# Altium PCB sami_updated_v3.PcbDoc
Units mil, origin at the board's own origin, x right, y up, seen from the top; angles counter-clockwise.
Board outline 1157.48 x 610 mil, 2 copper layers (Top Layer, Bottom Layer); 22 components, 24 nets, 105 pads, 51 vias.
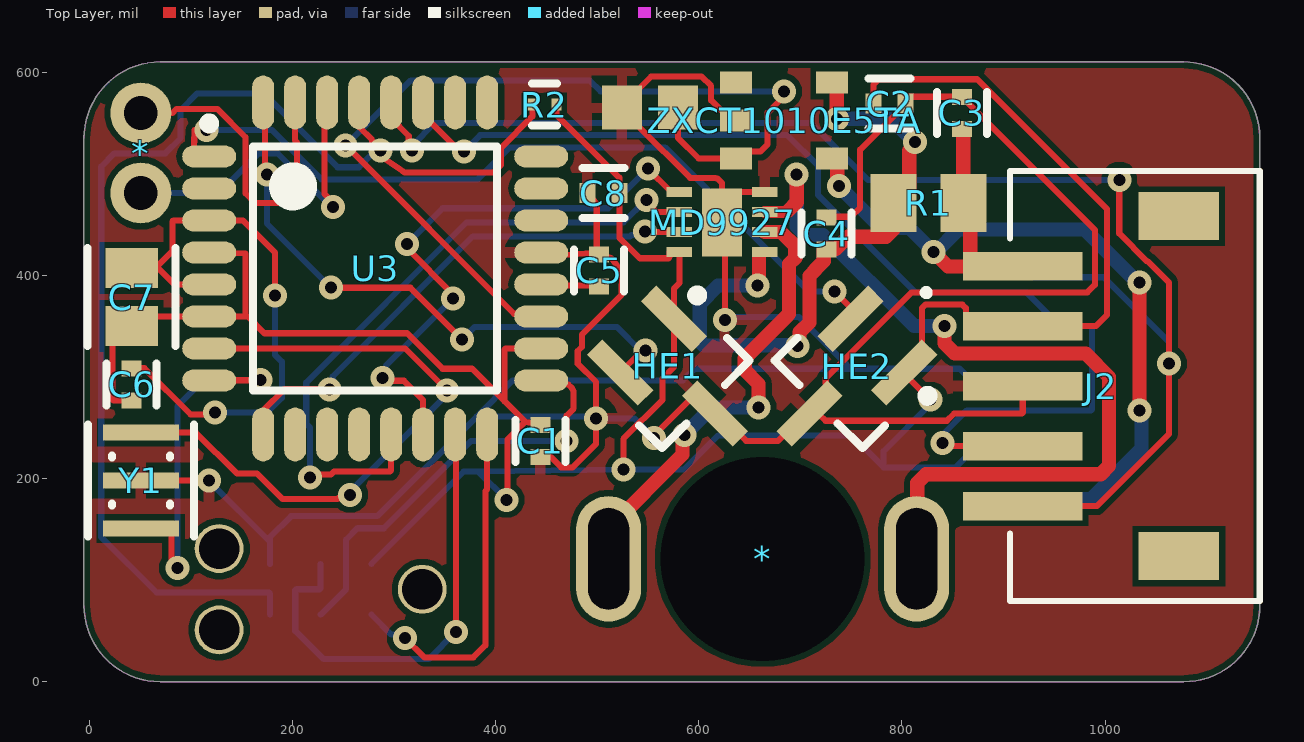
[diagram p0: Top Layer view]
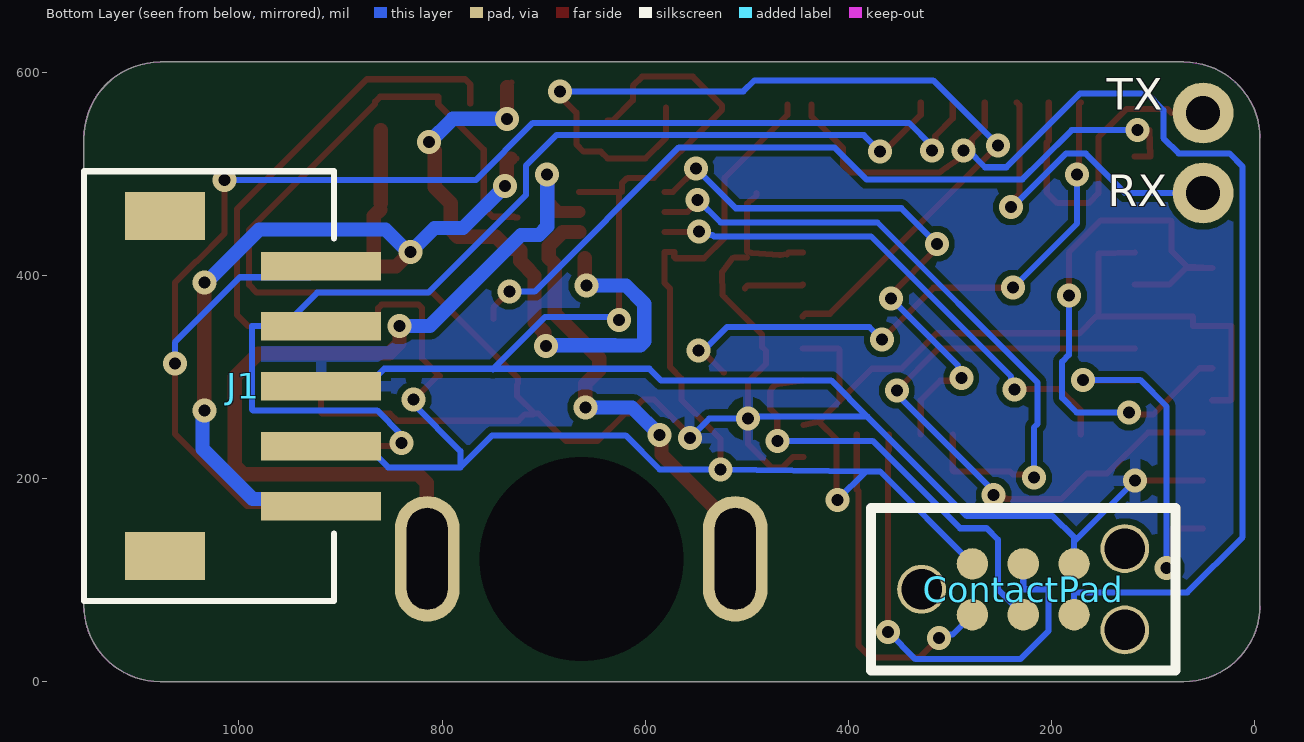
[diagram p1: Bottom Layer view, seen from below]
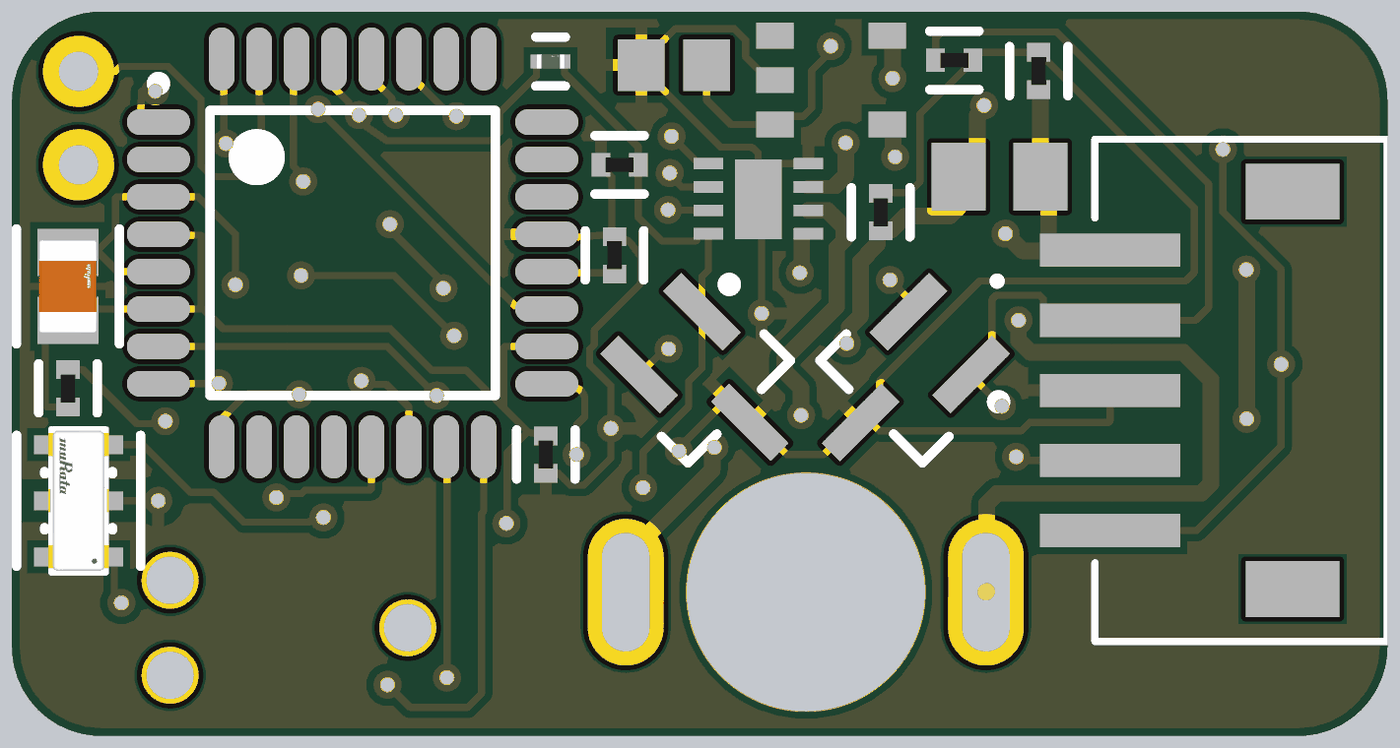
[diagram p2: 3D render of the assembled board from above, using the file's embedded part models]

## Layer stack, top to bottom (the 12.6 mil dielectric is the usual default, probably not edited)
Top Solder: solder mask 0.4, Solder Resist, Dk 3.5
Top Layer: signal copper 1.4
Dielectric 1: dielectric 12.6, FR-4, Dk 4.8
Bottom Layer: signal copper 1.4
Bottom Solder: solder mask 0.4, Solder Resist, Dk 3.5

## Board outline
-5,75 ccw(c70,75) 70,0 1077.48,0 ccw(c1077.48,75) 1152.48,75 1152.48,535 ccw(c1077.48,535) 1077.48,610 70,610 ccw(c70,535) -5,535

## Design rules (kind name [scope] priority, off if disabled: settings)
Clearance Clearance_1 [All] p1: gap=6 ignorepadtopadclearanceinfootprint=FALSE except(0: Arc-Hole Track-Hole SMDPad-Hole THPad-Hole Via-Hole Fill-Hole Poly-Hole Region-Hole Text-Hole)
HoleSize [All] p1: absolutevalues=TRUE maxlimit=100 minlimit=11.81 maxpercent=80.000 minpercent=20.000
MinimumAnnularRing [All] p1: minimumring=7.87
PolygonConnect [All] p1: connectstyle=Relief reliefconductorwidth=10 reliefentries=4 polygonreliefangle="90 Angle" airgapwidth=10
RoutingVias [All] p1: holewidth=11.81 width=23.62 viastyle="Through Hole" minholewidth=11.81 minwidth=23.62 maxholewidth=11.81 maxwidth=23.62
SolderMaskExpansion [All] p1: expansion=4 istentingtop=FALSE
Width [All] p1: maxlimit=15 minlimit=6 preferedwidth=6 minimp=50.000000 maximp=50.000000 favimp=50.000000
29 further rules are at their usual default settings.

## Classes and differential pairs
component class updated_sami_board_v3: 3 C1 C2 C3 C4 C5 C6 C7 C8 HE1 HE2 J1 J2 R1 R2 U3 Y1

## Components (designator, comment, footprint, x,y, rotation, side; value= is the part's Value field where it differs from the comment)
* "Component_1" "UART Header Pins" 51,481 r0 top
* "Poluou motor" PCBComponent_1 814.57,121 r180 top
C1 "GRM155R71C104KA88D - 0.1 uF -16V" FP-GRM15-MFG 444.25,237 r90 top value=0.10μF
C2 "GRM155R71C104KA88D - 0.1 uF - 16V" FP-GRM15-MFG 788,569 r180 top value=0.10μF
C3 "GRM155R71C104KA88D - 0.1 uF - 16V" FP-GRM15-MFG 859,560 r270 top value=0.10μF
C4 "GRM155R71C104KA88D - 0.1 uF - 16V" FP-GRM15-MFG 726,441 r270 top value=0.10μF
C5 "GRM155R71C104KA88D - 0.1 uF - 16V" FP-GRM15-MFG 502,404.75 r270 top value=0.10μF
C6 "GRM155R71C104KA88D - 0.1 uF - 16V" FP-GRM15-MFG 42,292.75 r270 top value=0.10μF
C7 "GRM21BR61E106KA73L - 10 uF -25V" FP-GRM21B-0_15-IPC_C 42,378.59 r90 top
C8 "GRM155R71C104KA88D - 0.1 uF - 16V" FP-GRM15-MFG 506.25,481 r0 top value=0.10μF
ContactPad "6 Pin Contact Pad" 6PinContactPad 18,71 r90 bottom
HE1 "TLE4946-2K" INF-PG-SC59_M 582.59,297.41 r315 top
HE2 "TLE4946-2K" INF-PG-SC59_M 742.41,297.41 r225 top
J1 "S5B-ZR-SM4A-TF (LF) (SN)" CONN_S5B-ZR-SM4A-TF_JST 919,172.83 r90 bottom
J2 "S5B-ZR-SM4A-TF (LF) (SN)" CONN_S5B-ZR-SM4A-TF_JST 919,409.11 r270 top
MD9927 "MD9927" MD9927 665.03,482 r180 top
R1 "RL1220S-R50-F - 0.5 Ohm 1/3W" RESC2013X50X40NL20T20 826,471 r180 top
R2 "ERJ-1GNF1002C - 10kOhm 1/20 W" FP-ERJ1G-MFG 448.19,568 r0 top value=10kΩ
R3 "ERA3AEB122V - 1.2 kOhm, 1/10W" RESC1608X55X30ML20T20 552,565 r0 top
U3 "ATmega328-AU" 32A_L 281.61,406.76 r0 top
Y1 "CSTNE16M0V53C000R0 - 16 MHz Crystal" FP-CSTNE16M0V53C000R0-MFG 51,198 r270 top
ZXCT1010E5TA "ZXCT1010E5TA" ZXCT1010E5TA 731.49,515 r90 top

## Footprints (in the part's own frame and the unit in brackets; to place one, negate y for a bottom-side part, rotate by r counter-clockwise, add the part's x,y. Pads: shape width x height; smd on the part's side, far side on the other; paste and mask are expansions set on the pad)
6PinContactPad [mil]
  round 30.98 smd: 1(-5,260) 2(45,260) 3(-5,210) 4(45,210) 5(-5,160) 6(45,160)
  round 48 hole 40 unplated: 25(20,310) 26(-20,110) 27(60,110)
  silkscreen extent -60,60 100,360
32A_L [mm] "Thin QFP, 32-Leads, Body 7x7mm, Pitch 0.8mm, IPC High Density"
  oval 1.35x0.55 smd: 1(-4.15,2.8) 2(-4.15,2) 3(-4.15,1.2) 4(-4.15,0.4) 5(-4.15,-0.4) 6(-4.15,-1.2) 7(-4.15,-2) 8(-4.15,-2.8) 17(4.15,-2.8) 18(4.15,-2) 19(4.15,-1.2) 20(4.15,-0.4) 21(4.15,0.4) 22(4.15,1.2) 23(4.15,2) 24(4.15,2.8)
  oval 0.55x1.35 smd: 9(-2.8,-4.15) 10(-2,-4.15) 11(-1.2,-4.15) 12(-0.4,-4.15) 13(0.4,-4.15) 14(1.2,-4.15) 15(2,-4.15) 16(2.8,-4.15) 25(2.8,4.15) 26(2,4.15) 27(1.2,4.15) 28(0.4,4.15) 29(-0.4,4.15) 30(-1.2,4.15) 31(-2,4.15) 32(-2.8,4.15)
  silkscreen extent -4.27,-3.05 3.05,3.75, body extent -3.5,-3.5 3.5,3.5, height 1.2
CONN_S5B-ZR-SM4A-TF_JST [mil]
  rect 28x118 smd paste+0 mask+0: 1(0,0) 2(59.06,0) 3(118.11,0) 4(177.17,0) 5(236.22,0)
  rect 47x79 smd: 6(-49.21,153.62) 7(285.43,153.62)
  silkscreen extent -93,-13 330,233, body extent 0,0 10,10, height 10
FP-CSTNE16M0V53C000R0-MFG [mm]
  rect 0.4x1.9 smd paste+0 mask+0: 1(-1.2,0) 2(0,0) 3(1.2,0)
  silkscreen extent -1.4,-1.33 1.4,1.33, body extent -1.6,-0.65 1.6,0.65, height 1
FP-ERJ1G-MFG [mm]
  rect 0.25x0.3 smd paste+0 mask+0: 1(-0.3,0) 2(0.3,0)
  silkscreen extent -0.32,-0.53 0.32,0.53, body extent -0.53,-0.27 0.53,0.27, height 0.25
FP-GRM15-MFG [mm]
  rect 0.4x0.5 smd paste+0 mask+0: 1(-0.4,0) 2(0.4,0)
  silkscreen extent -0.53,-0.62 0.53,0.62, body extent -0.7,-0.38 0.7,0.38, height 0.25
FP-GRM21B-0_15-IPC_C [mil]
  rect 39.6x51.5 smd paste+0 mask+0: 1(-28.59,0) 2(28.59,0)
  silkscreen extent -48,-43 48,43, body extent -39,-25 39,25, height 55
INF-PG-SC59_M [mm] "SOT23, 3-Leads, Body 3x1.53mm, Pitch 0.95mm, IPC Low Density"
  rect 1.8x0.55 smd: 1(-1.2,0.95) 2(-1.2,-0.95) 3(1.2,0)
  silkscreen extent -1.32,-1.55 0.88,1.9, body extent -0.88,-1.55 0.88,1.55, height 1.35
MD9927 [mm]
  rect 0.635x0.25 smd mask+0: GND(0,0) IN1(2.135,0.5) IN2(2.135,0) nSLEEP(2.135,1) OUT1(0,1) OUT2(0,0.5) VCC(2.135,1.5) VM(0,1.5)
  rect 1x1.7 smd mask+0: GND(1.068,0.762)
PCBComponent_1 [mm]
  round 0 hole 5.1: 28(3.85,0)
  rrect100% 1.62x3.14 hole 1.02 slot 2.54 at 90 deg: m+(7.7,0) m-(0,0)
RESC1608X55X30ML20T20 [mm] "Chip Resistor, 2-Leads, Body 1.60x0.80mm, IPC Low Density"
  rect 1x1.1 smd: 1(-0.7,0) 2(0.7,0)
  body extent -0.9,-0.5 0.9,0.5, height 0.55
RESC2013X50X40NL20T20 [mm] "Chip Resistor, 2-Leads, Body 2.00x1.25mm, IPC Medium Density"
  rect 1.15x1.45 smd: 1(-0.875,0) 2(0.875,0)
  body extent -1.1,-0.72 1.1,0.72, height 0.5
"UART Header Pins" [mil]
  round 60 hole 33.23: RX(0,0) TX(0,78.74)
ZXCT1010E5TA [mm]
  rect 0.55x0.8 smd mask+0: GND(0.95,2.4) IOUT(0,2.4) NC(1.9,2.4) VSENSE+(0,0) VSENSE-(1.9,0)

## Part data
C1 C2 C3 C4 C5 C6 C8: library part CMP-2100-03641-2, "CAP CER 0.1UF 16V X7R 0402", Capacitance=0.10μF, Manufacturer=Murata, Manufacturer Part Number=GRM155R71C104KA88D, Package=GRM15, Temperature="-55°C to +125°C", Temperature Characteristic=X7R, Temperature Range High=+125°C, Temperature Range Low=-55°C, Tolerance=10%, Voltage Rating=16Vdc
C7: library part CMP-2007-03541-2, "Chip Multilayer Ceramic Capacitors for General Purpose, 0805, 10uF, X5R, 15%, 10%, 25V", Capacitance=10uF, Case Code (Imperial)=0805, Case Code (Metric)=2012, Dielectric=X5R, Max Operating Temperature=85°C, Min Operating Temperature=-55°C, Package Quantity=1, Tolerance=10%, Voltage=25V
HE1 HE2: library part CMP-1148-00006-1, "High Precision Hall Effect Latch, PG-SC59, Reel, Green", Manufacturer=Infineon
J1 J2: "No Description Available", Mfr_Name=JST
R1: library part CMP-2001-03168-1, Manufacturer=Susumu, Part Number=RL1220S-R50-F
R2: library part CMP-2004-03445-2, "RES SMD 10K OHM 1% 1/20W 0201", Manufacturer="Panasonic Electronic Components", Manufacturer Part Number=ERJ-1GNF1002C, Package=ERJ1G, Power Rating=0.05W, Resistance=10kΩ, Temperature="-55°C to +125°C", Temperature Coefficient=200ppm/°C, Temperature Range High=+125°C, Temperature Range Low=-55°C, Tolerance=1%, Voltage Rating=25V
R3: library part CMP-2000-00897-1, Manufacturer=Panasonic, Part Number=ERA3AEB122V
U3: library part CMP-0095-00261-2, "8-bit AVR Microcontroller, 32KB Flash, 1KB EEPROM, 2KB SRAM, 32-pin TQFP, Industrial Grade (-40°C to 85°C)"
Y1: library part CMP-06057-000009-1, "CERAMIC RES 16.0000MHZ 15PF SMD", Capacitance=15pF, Case/Package=SMD/SMT, Frequency=16MHz, Frequency Stability=0.15%, Frequency Tolerance=0.5%, Max Operating Temperature=125°C, Min Operating Temperature=-40°C, Resistor Type=Ceramic

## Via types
v1: diameter 23.62, hole 11.81, Top Layer to Bottom Layer, tented both sides, 51 vias

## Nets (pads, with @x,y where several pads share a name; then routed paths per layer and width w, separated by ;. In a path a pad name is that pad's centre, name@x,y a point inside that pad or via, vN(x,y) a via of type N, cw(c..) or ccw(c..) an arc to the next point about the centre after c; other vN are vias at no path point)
CUR1_TO_OPAMP_IN+: C4.2 MD9927.VM R1.2 ZXCT1010E5TA.VSENSE- | length 627.8
  Top Layer w6: ZXCT1010E5TA.VSENSE- ZXCT1010E5TA.VSENSE-@736,585.29
  Top Layer w14: v1(658,390) 659.53,391.53 659.53,416.87 ; v1(697.5,330.56) 699.34,332.4 699.34,344.03 709,353.68 709,399.45 715.04,405.48 715.04,405.97 723.16,414.09 723.16,424.38 724.91,426.13 735.13,426.13 746.97,437.97 784.52,437.97 791.55,445 R1.2 807.19,486.64 807.19,522.59 813,528.4 v1(813,531) ; v1(736,554) ZXCT1010E5TA.VSENSE-@736,585.29
  Bottom Layer w6: 630.04,331 630.11,331.06
  Bottom Layer w14: 630.04,331 605,331 601,335 601,372 619,390 v1(658,390) ; 630.11,331.06 697,331.06 v1(697.5,330.56) ; v1(736,554) 789.6,554 812.6,531 v1(813,531)
CURRENT_IN: R3.2 U3.19 ZXCT1010E5TA.IOUT | length 915.5
  Top Layer w6: v1(252.6,527.83) 418.28,362.15 442.37,362.15 U3.19 ; R3.2 579.56,535.44 600,515 ZXCT1010E5TA.IOUT 643.82,521.82 660.82,521.82 667.88,528.88 667.88,560.12 684,576.23 v1(684,581)
  Bottom Layer w6: v1(252.6,527.83) 316.72,591.94 492.5,591.94 503.44,581 v1(684,581)
GND: C1.1 C2.1 C3.1 C4.1 C5.1 C8.1 ContactPad.6 HE1.3 HE2.3 J1.3 J2.3 MD9927.GND R3.1 U3.21 Y1.2 ZXCT1010E5TA.GND | length 3440.6
  Top Layer w6: Y1.2 v1(118,198) ; C1.1 454.5,221.25 464.75,211 476,211 499,234 v1(499,259) 499,295 481.03,312.97 481.03,325.49 485,329.46 485,341.56 521.55,378.11 524.01,380.57 524.09,383 524.48,400.92 524.48,400.99 524.48,403.03 515.29,415.49 513.69,417.09 512.02,417.57 C5.1@499.92,417.57 ; U3.21 458.78,422.51 459.01,422.27 460.5,420.78 467.06,420.05 467.4,420.01 467.95,420.01 494.94,421.99 495.16,421.99 499.75,423.62 499.75,470.64 496.24,474.16 495.38,474.16 490.5,479.03 C8.1 ; v1(556.17,239.83) 556.17,242.6 591.25,277.68 602.32,277.68 HE1.3 619.87,264 646.87,237 678.13,237 705.13,264 HE2.3 ; v1(625.81,355.81) MD9927.GND@625.81,479.19 ; ZXCT1010E5TA.GND 632.08,552.4 612.25,572.23 612.25,586.37 602.97,595.65 553.13,595.65 524.44,566.97 R3.1 524.44,563.03 541.13,546.35 591.59,495.92 616.78,495.92 617.52,495.17 618.64,495.17 622.86,490.95 622.86,482.46 623.33,482 MD9927.GND@665.03,482 ; C4.1 728.25,456.75 729.13,457.63 749.97,457.63 759,466.66 759,523.75 803.75,568.5 C2.1 803.75,575.75 860.97,575.75 865.84,570.87 865.84,568.91 990,444.75 990,390.51 982.71,383.22 809.55,383.22 725.08,298.76 725.08,293.78 726.4,292.47 726.4,281.4 HE2.3 ; J2.3 919,265 918,264 851.43,264 844.27,256.84 724.91,256.84 718.91,262.84 710.16,262.84 HE2.3
  Bottom Layer w6: v1(118,198) 178,138 ; ContactPad.6 178,138 ; v1(556.17,239.83) 537,259 v1(499,259) 497,261 381.45,261 ; v1(625.81,355.81) 629,359 698.5,359 750,307.5 ; J1.3 874,290.94 856.94,308 596,308 584.58,296.58 417.02,296.58 381.45,261 ; 178,138 178,142 199.04,163.04 283.49,163.04 381.45,261
INPUT1: MD9927.IN1 U3.13 | length 660.7
  Top Layer w6: v1(217.41,200.81) 220.6,204 238.22,204 241.22,207 296.36,207 297.36,208 U3.13 ; v1(548.47,474.04) 548.47,472.53 558.68,462.32 MD9927.IN1
  Bottom Layer w6: v1(217.41,200.81) 217.41,250.24 213.81,253.84 213.81,294.38 371.43,452 525.86,452 547.91,474.04 v1(548.47,474.04)
INPUT2: MD9927.IN2 U3.14 | length 570
  Top Layer w6: v1(289,299) 291.81,296.19 309.81,296.19 328.86,277.14 U3.14 ; v1(313,431) 313,426.5 358,381.5 v1(358,377) ; v1(550,505) 573,482 MD9927.IN2
  Bottom Layer w6: v1(289,299) 292.37,302.37 292.37,311.37 v1(358,377) ; v1(313,431) 348,466 511,466 v1(550,505)
INPUT3: MD9927.nSLEEP U3.9 | length 512
  Top Layer w6: U3.9 171.38,267 192.38,288 236.22,288 v1(236.54,287.68) ; v1(547,443) 547.18,442.82 580.79,442.82 MD9927.nSLEEP
  Bottom Layer w6: v1(236.54,287.68) 239.92,291.05 239.92,300.42 377.82,438.32 532.56,438.32 533.86,439.63 543.63,439.63 v1(547,443)
M+: *.m+ MD9927.OUT1 | length 457.8
  Top Layer w6: *.m+ *.m+@511.43,141.11 ; 687.66,360.62 689,361.97
  Top Layer w14: *.m+@511.43,141.11 511.43,150.92 584.16,223.65 584.16,241.16 v1(586,243) ; v1(659,270) 659,293 645.31,306.69 645.31,318.28 687.66,360.62 ; MD9927.OUT1 681.15,442.63 695.04,428.74 695.04,417.15 689,411.11 689,361.97
  Bottom Layer w14: v1(586,243) 613,270 658.84,270 v1@658.92,269.92
M-: *.m- MD9927.OUT2 | length 856
  Top Layer w6: 687,462.32 688,463.32 ; 842.56,332.56 845.84,329.28
  Top Layer w12: MD9927.OUT2 687,462.32
  Top Layer w14: 688,463.32 696.5,471.82 v1(696.5,499.46) ; *.m- 815.18,121.61 815.18,195.61 823.82,204.25 995.75,204.25 1004,212.5 1004,300 980.94,323.06 852.06,323.06 842,333.12 v1(842,350)
  Bottom Layer w6: v1@696.5,497.64 v1(696.5,499.46)
  Bottom Layer w14: v1@696.5,497.64 696.5,447.98 704.7,439.77 722.46,439.77 812.23,350 v1(842,350)
MISO: ContactPad.1 U3.16 | length 342.7
  Top Layer w6: v1(311,43) 330,24 378.35,24 390.19,35.84 390.19,187.62 391.85,189.28 U3.16
  Bottom Layer w6: ContactPad.1 297.63,46.37 307.63,46.37 v1(311,43)
MOSI: ContactPad.4 U3.15 | length 465.1
  Top Layer w6: U3.15 360.35,228 361,227.35 v1(361,49)
  Bottom Layer w6: ContactPad.4 228,92 227,91 204,91 203,90 203,50 230.81,22.19 334.19,22.19 v1(361,49)
MOTOR1_IN: C3.2 J1.1 J2.1 R1.1 ZXCT1010E5TA.VSENSE+ | length 924.6
  Top Layer w6: ZXCT1010E5TA.VSENSE+@727,515 ZXCT1010E5TA.VSENSE+ ; C3.2 C3.2@860.45,542.8
  Top Layer w14: ZXCT1010E5TA.VSENSE+@732.52,515 736.35,511.17 736.35,489.58 v1(738.19,487.74) ; v1(831,423) 845.45,408.55 J2.1@878.29,408.55 ; R1.1 C3.2@860.45,542.8 ; R1.1@860.93,464.61 867.23,458.31 867.23,416.11 874.23,409.11 J2.1 ; v1(1033.72,392.72) 1034,392.43 v1(1034,267)
  Bottom Layer w14: v1(738.19,487.74) 779.35,446.58 807.42,446.58 817.35,436.65 v1(831,423) 833.6,423 855.6,445 980,445 1032.28,392.72 v1(1033.72,392.72) ; J1.1 926,179.83 986.3,179.83 1035.84,229.37 1035.84,265.16 v1(1034,267)
NetC5_2: C5.2 U3.20 | length 58.6
  Top Layer w6: U3.20 446.01,390.01 499.24,390.01 C5.2@502,387.25
NetC6_1: C6.1 C7.2 U3.3 U3.5 | length 593.3
  Top Layer w6: C6.1 54.5,308.5 100,263 122,263 v1(124,265) ; U3.5 84,391.02 C7.2@66.55,408.46 ; v1(183,380) 183,422.5 151.49,454.01 83,454.01 82,453.01 82,423.91 C7.2@66.55,408.46 ; C7.2@66.55,408.46 65.28,407.18 C7.2 C7.2@66.55,408.46
  Bottom Layer w6: v1(124,265) 175.3,265 189.81,279.51 189.81,314.97 183,321.78 v1(183,380)
NetU3_7: U3.7 Y1.1 | length 628.1
  Top Layer w6: Y1.1 105.2,245.24 145.44,205 165.24,205 190.24,180 244.7,180 245.31,180.61 253.66,180.61 v1(257.03,183.98) ; U3.7 310.98,328.02 v1(352.37,286.63)
  Bottom Layer w6: v1(257.03,183.98) 257.03,187.66 352.37,283 v1(352.37,286.63)
NetU3_8: U3.8 Y1.3 | length 374
  Top Layer w6: Y1.3 81,150.76 81,118 v1(87,112) ; U3.8 118.46,296.76 168.76,296.76 v1(169,297)
  Bottom Layer w6: v1(87,112) 87,271 113,297 v1(169,297)
Q1: HE1.2 U3.32 | length 587.9
  Top Layer w6: U3.32 173.19,568.34 173.19,500.81 v1(175,499) ; v1(238.21,387.8) 316.2,387.8 v1(367,337) ; HE1.2 544.34,325.97 v1(547.53,325.97)
  Bottom Layer w6: v1(175,499) 175,451.01 237,389.01 v1@237,388 ; v1(367,337) 367.33,337 379.33,349 519.73,349 542.77,325.97 v1(547.53,325.97)
Q2: HE2.2 U3.1 | length 796.3
  Top Layer w6: v1(115.5,543) 104,543 103.02,517.58 103,517 U3.1 ; v1(733.81,384) 749.42,368.39 HE2.2 HE2.2
  Bottom Layer w6: v1(115.5,543) 180.22,543 210.51,512.71 228.8,494.41 382.41,494.41 414,526 567,526 709,384 v1(733.81,384)
RESET: ContactPad.5 R2.1 U3.29 | length 1202.2
  Top Layer w6: U3.29 265.87,546 278.63,533.24 278.63,521.37 282,518 v1@285.46,518 ; v1(286.93,522.93) 285.46,521.46 v1@285.46,518 ; R2.1 436.38,556.38 405.22,525.22 405.22,508.47 397.94,501.19 312.5,501.19 310.64,501.19 309.11,502.24 303.65,505.98 288.98,516.03 285.82,519.19 v1@285.46,518
  Bottom Layer w6: ContactPad.5 178,87 177,88 66.38,88 12,142.38 12,507 25,520 75,520 90,535 90,562.5 106.5,579 172,579 244.59,506.41 265.65,506.41 282.16,522.93 v1(286.93,522.93)
RX: *.RX U3.30 | length 334.6
  Top Layer w6: U3.30 231.79,567.57 231.79,479.98 240,471.77 v1(240,467)
  Bottom Layer w6: *.RX 127.57,481 166.38,519.81 186,519.81 238.81,467 v1(240,467)
SCK: ContactPad.3 U3.17 | length 428.8
  Top Layer w6: U3.17 471.93,292.32 475.07,289.18 477,285.47 477,268.86 470.07,261.93 v1(470.07,237)
  Bottom Layer w6: ContactPad.3 253,91 253,139.97 264.07,151.04 290.21,151.04 376.17,237 v1(470.07,237)
SCL: J1.5 J2.5 U3.28 | length 1450.5
  Top Layer w6: U3.28 297.36,554.4 314.63,537.14 314.63,526.37 v1(318,523) ; J2.5 991.89,172.89 1063,244 v1(1063,313) 1063,392.86 1042.34,413.53 1041.69,413.53 1014,441.22 v1(1014,494)
  Bottom Layer w6: v1(318,523) 318,527.55 340.45,550 710.57,550 766.57,494 v1(1014,494) ; J1.5@897.46,409.05 J1.5 930,398.05 998.95,398.05 1063,334 v1(1063,313)
SDA: J1.4 J2.4 U3.27 | length 1114.4
  Top Layer w6: U3.27 328.86,557.86 364.72,522 v1(369,522) ; v1(840,235) 843.05,231.95 J2.4
  Bottom Layer w6: v1(369,522) 385,538 687.43,538 717.31,508.12 717.31,479.18 813.5,383 817.98,383 922.82,383 955.82,350 987,350 987,268 986,267 864,267 840,243 v1(840,235)
TX: *.TX U3.31 | length 320.3
  Top Layer w6: *.TX 82.01,559.74 86.08,563.81 126.17,563.81 154,535.99 154,480.57 163.57,471 194.43,471 204.81,481.38 204.81,530.69 202.87,532.63 U3.31
VCC: C1.2 C2.2 C6.2 C7.1 C8.2 ContactPad.2 HE1.1 HE2.1 J1.2 J2.2 MD9927.VCC R2.2 U3.4 U3.6 U3.18 | length 2857.5
  Top Layer w6: C6.2 24,277 23,278 23,350 C7.1 61,350 61,359.52 U3.6 154,359.52 ; U3.4 154,421.51 154,359.52 ; v1(411,179) 411.68,179.68 411.68,238.42 429.13,255.87 ; C1.2 432.74,255.13 429.13,255.87 ; U3.18 410,328.02 409,327.02 409,276 ; R2.2 460,558 522,496 C8.2 522,437 542.21,416.79 570.27,416.79 571.47,418 571.47,422.94 MD9927.VCC 580.97,392.34 575.63,387 HE1.1 575.63,309.64 564.45,298.45 564.45,277.54 526,239.09 v1(526,209) ; C2.2 772.25,588 777.25,593 874,593 1002,465 1002,361.06 991,350.06 874,350.06 863,361.06 863,367.7 859.49,371.22 823.17,371.22 819.66,367.7 819.66,318.14 802.26,300.74 804.91,300.74 v1(828,277.65) ; 154,359.52 156,359.52 172.52,343 313,343 348,308 377,308 409,276 ; 409,276 429.13,255.87
  Bottom Layer w6: ContactPad.2 368.4,206.4 ; 368.82,206.82 383.18,206.82 v1(411,179) ; 383.78,207.03 v1(526,209) 586,209 619.39,242.39 750.61,242.39 782,211 ; v1(828,277.65) 828,272.95 782,226.95 782,211 ; J1.2 874,231.89 853.11,211 782,211
pads on no net: *.28 ContactPad.25 ContactPad.26 ContactPad.27 J1.6 J1.7 J2.6 J2.7 U3.2 U3.10 U3.11 U3.12 U3.22 U3.23 U3.24 U3.25 U3.26 ZXCT1010E5TA.NC

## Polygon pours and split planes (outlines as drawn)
GND on Bottom Layer "GND_L02_P000" (solid, remove dead copper, pour order 0): -131,692 -87,648 1374,648 1374,-117 1296,-195 1291,-190 -165,-190
GND on Top Layer "GND_L01_P001" (solid, remove dead copper, pour order 1): -122,665 1179,665 1300,544 1300,-209 -150,-209 -155,-214

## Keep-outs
Keep-Out Layer:
  the board outline again, w0.51

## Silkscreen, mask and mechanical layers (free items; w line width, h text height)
Top Overlay:
  circle w10: c824,383 r1.41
